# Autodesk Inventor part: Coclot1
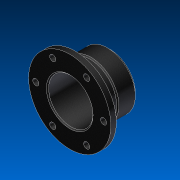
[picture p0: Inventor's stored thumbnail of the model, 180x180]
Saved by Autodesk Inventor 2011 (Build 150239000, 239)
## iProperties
Created: 2011-05
Part Number: Coclot1
Document SubType Name: Modeling
Designer: 904Chiaki
Density: 1 g/cm^3
Mass: 282.321 g
Surface Area: 676.471 cm^2
Volume: 282.321 cm^3
Author: 904Chiaki
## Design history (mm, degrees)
sketch "Sketch1"
  geometry: L1 (-36.619, 18.132)-(-36.619, -16.285); L2 (3.381, 57.601)-(3.381, -15.399); L3 (3.381, 57.601)-(13.381, 57.601); L4 (13.381, -5.399)-(37.381, -5.399); L5 (37.381, -5.399)-(37.381, -15.399); L6 (37.381, -15.399)-(3.381, -15.399); L7 (13.381, 57.601)-(13.381, 21.101); L8 (13.381, 11.953)-(13.381, -3.399); L9 (13.381, -3.399)-(12.381, -3.399); L10 (13.381, -5.399)-(12.381, -5.399); L11 (12.381, -5.399)-(12.381, -3.399); L12 (13.381, 11.953)-(11.381, 11.953); L13 (11.381, 11.953)-(11.381, 21.101); L14 (13.381, 21.101)-(11.381, 21.101); 1 further point
  constraints: 28 end point
  dimensions: "d0" = 73 distance of L2.start L2.end; "d1" = 40 distance between parallel lines of L1 L2; "d2" = 10 distance of L2.start L3.end; "d3" = 63 distance of L3.end L4.start; "d4" = 24 distance of L4.start L4.end; "d16" = 1 distance of L8.end L9.end; "d37" = 2 distance between parallel lines of L7 L13
revolve "Revolution1" sketch "Sketch1" stored, may be unused: angle "d17" = 90 deg
chamfer "Chamfer1" distance "d18" = 0.5; stored, may be unused: second distance "d19" = 2, angle "d20" = 45 deg
chamfer "Chamfer2" distance "d21" = 5; stored, may be unused: second distance "d22" = 2, angle "d23" = 45 deg
chamfer "Chamfer3" distance "d24" = 2; stored, may be unused: second distance "d25" = 2, angle "d26" = 45 deg
workplane "Work Plane1"
node "Hole2"
chamfer "Chamfer4" distance "d38" = 2; stored, may be unused: second distance "d39" = 2, angle "d40" = 45 deg
body "Solid1"
sketch "Sketch2"
  geometry: 6 further points
hole "Hole1" sketch "Sketch2" diameter "d28" = 11; stored, may be unused: countersink angle "d32" = 90 deg, drill point angle "d34" = 0 deg; dims "d29" = 6, "d30" = 4, "d31" = 2, "d33" = 8
